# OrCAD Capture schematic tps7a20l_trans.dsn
size A; title: TPS7A20L 300mA, Low-Noise, Low-IQ, High-PSRR; rev: 1.0; note: SBVS151E –DECEMBER 2010–REVISED MAY 2015
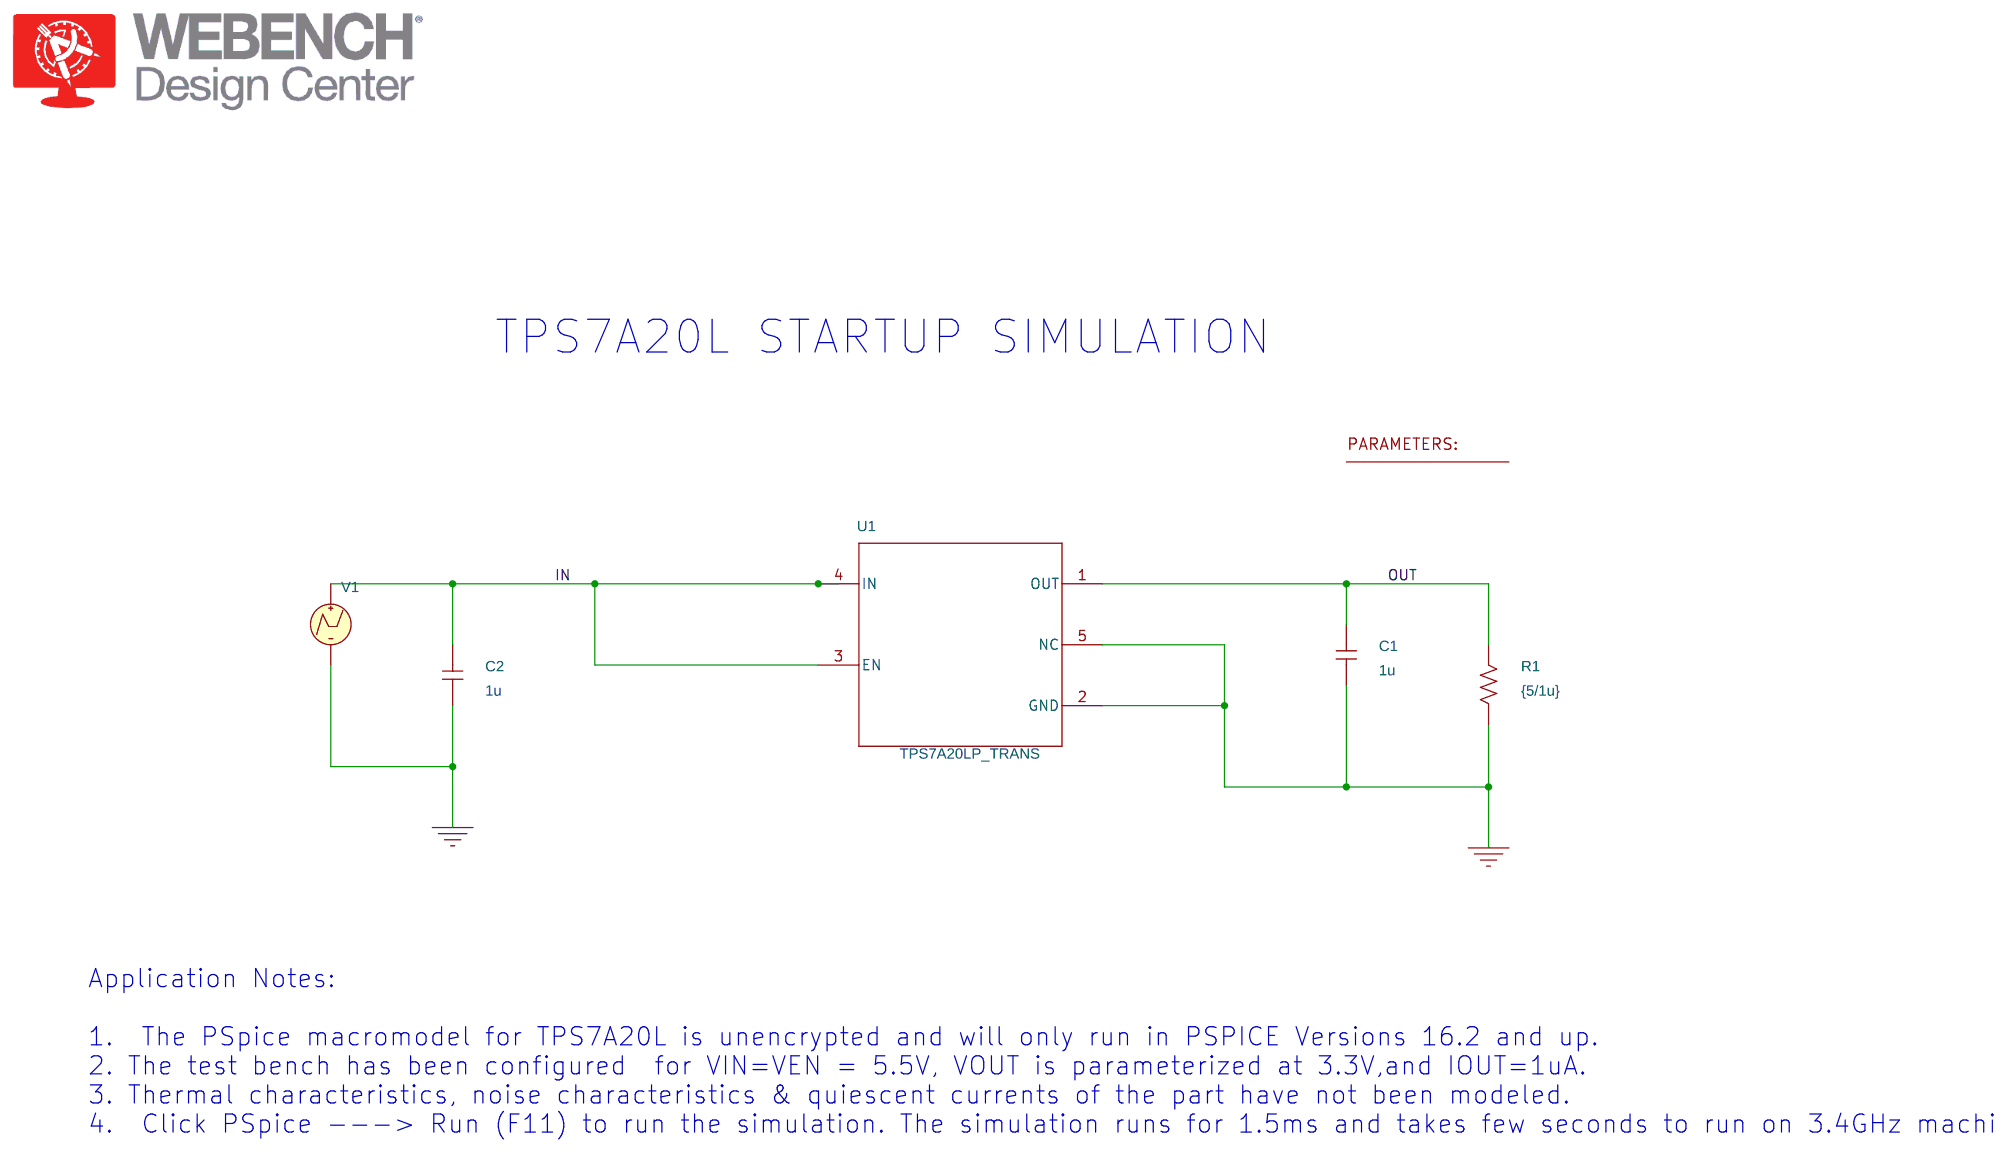
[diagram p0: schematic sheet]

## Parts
1  PARAM
C1  1u  [RAD/CK05]
C2  1u  [RAD/CK05]
R1  {5/1u}  [AX/RC05]
U1  TPS7A20LP_TRANS  [DQN0005A_N]
V1  VPWL

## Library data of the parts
1 = PARAM: VOUT: 3.3
C1 C2 = C
R1 = R
U1 = TPS7A20L_TRANS
V1 = VPWL: PSpiceTemplate: V^@REFDES %+ %- ?DC|DC @DC| ?AC|AC @AC|\n+PWL @T1 @V1 @T2 @V2 #T3/@T3 @V3/ #T4/@T4 @V4/ #T5/@T5 @V5/ #T6/@T6 @V6/ #T7/@T7 @V7/ #T8/@T8 @V8/ #T9/@T9 @V9/ #T10/@T10 @V10/; T1: 0; T2: 100u; T3: 100.1u; V1: 0; V2: 0; V3: 5.5

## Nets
0: C1.1 C2.1 R1.1 U1.2(GND) U1.5(NC) V1.2(-)
IN: C2.2 U1.3(EN) U1.4(IN) V1.1(+)
OUT: C1.2 R1.2 U1.1(OUT)

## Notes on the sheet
- TPS7A20L STARTUP SIMULATION
- Application Notes:
  1.  The PSpice macromodel for TPS7A20L is unencrypted and will only run in PSPICE Versions 16.2 and up.
  2. The test bench has been configured  for VIN=VEN = 5.5V, VOUT is parameterized at 3.3V,and IOUT=1uA.
  3. Thermal characteristics, noise characteristics & quiescent currents of the part have not been modeled.
  4.  Click PSpice ---> Run (F11) to run the simulation. The simulation runs for 1.5ms and takes few seconds to run on 3.4GHz machine.
